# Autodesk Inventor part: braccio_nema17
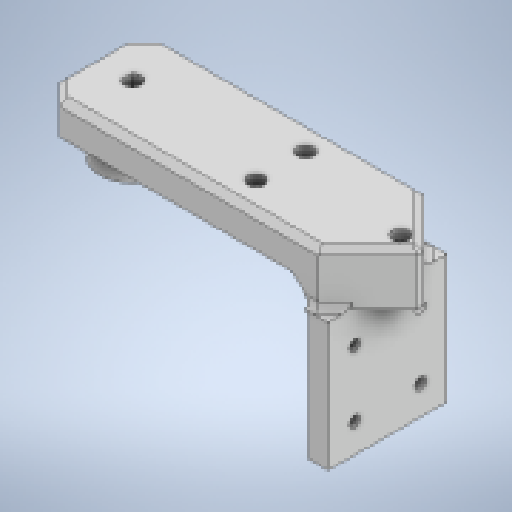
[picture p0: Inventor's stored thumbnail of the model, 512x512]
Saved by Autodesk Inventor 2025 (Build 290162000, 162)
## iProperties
Created: 2025-11
Part Number: braccio_nema17
Material: Generico
Document SubType Name: Modeling
Designer: R5800u
Density: 1 g/cm^3
Appearance: Default
Author: R5800u
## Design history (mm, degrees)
sketch "Schizzo1"
  geometry: L1 (2, 1.582)-(2, -1.582); C1 r 10 at (0, 0); A1 r 2.55 centre (0, 0) between (2, 1.582) and (2, -1.582); 1 further point
  constraints: 2 centre point, 2 coincident, 2 end point, 2 point on circle, 1 vertical
  dimensions: "d0" = 20 diameter of C1; "d1" = 5.1 diameter of A1; "d2" = 2 distance from line of point (0, 0) L1
extrude "Estrusione1" new body sketch "Schizzo1" distance "d3" = 20; taper "d4" = 0 deg
sketch "Schizzo2"
  geometry: L1 (-12.5, -16)-(87.5, -16); L2 (87.5, -16)-(87.5, 16); L3 (87.5, 16)-(-12.5, 16); L4 (-12.5, 16)-(-12.5, -16); L5 (0, 0)-(107, 0) reference; C1 r 10 at (0, 0) reference; C2 r 2.55 at (0, 0) reference; 1 further point
  constraints: 10 end point, 3 horizontal, 2 parallel, 1 perpendicular, 1 other
  dimensions: "d5" = 100 distance of L3.end L2.end
extrude "Estrusione2" join sketch "Schizzo2" distance "d6" = 10; taper "d7" = 0 deg
sketch "Schizzo3"
  geometry: L1 (18.5, -5)-(13.5, -5); L2 (13.5, -5)-(13.5, -15); L3 (13.5, -15)-(18.5, -15); L4 (18.5, -15)-(18.5, -5); L5 (6, -10)-(26, -10) reference; L6 (18.5, -5)-(13.5, -15); L7 (13.5, -5)-(18.5, -15); L8 (32, -10)-(0, -10) reference; 4 further points
  constraints: 12 end point, 3 midpoint, 2 parallel, 1 horizontal, 1 perpendicular
  dimensions: "d8" = 5 distance of L3.end L2.end
extrude "Estrusione3" join sketch "Schizzo3" stored distance "d9" = 10; taper "d10" = 0 deg
chamfer "Smusso1" distance "d11" = 6; stored, may be unused: second distance "d12" = 2, angle "d13" = 45 deg
sketch "Schizzo4"
  geometry: L1 (-6.5, -16)-(87.5, -16) reference; L2 (77.5, -16)-(77.5, 16); L3 (87.5, -16)-(87.5, -2.5) reference; L4 (87.5, 16)-(-6.5, 16) reference; L5 (77.5, -16)-(87.5, -16); L6 (87.5, -16)-(87.5, 16); L7 (87.5, 16)-(77.5, 16); L8 (77.5, 16)-(77.5, -16); 2 further points
  constraints: 10 end point, 2 parallel, 1 horizontal, 1 perpendicular, 1 point on line, 1 vertical
  dimensions: "d14" = 10 distance between parallel lines of L3 L2
node "Piano di lavoro1"
extrude "Estrusione4" join sketch "Schizzo4" stored distance "d15" = 10; taper "d16" = 0 deg
sketch "Schizzo5"
  geometry: L1 (77.5, -16)-(77.5, -2.5) reference; L2 (-6.5, 16)-(87.5, 16) reference; L3 (77.5, -16)-(69.5, -16); L4 (69.5, -16)-(69.5, 16); L5 (69.5, 16)-(77.5, 16); L6 (77.5, 16)-(77.5, -16); 3 further points
  constraints: 8 end point, 2 parallel, 1 horizontal, 1 perpendicular, 1 point on line
  dimensions: "d17" = 8 distance of L4.end L5.end
node "Piano di lavoro2"
extrude "Estrusione5" join sketch "Schizzo5" stored distance "d18" = 10; taper "d19" = 0 deg
sketch "Schizzo6"
  geometry: C1 r 1.45 at (6, -16.1) reference; C2 r 1.45 at (26, -16.1) reference; C3 r 1.45 at (6, -36.1) reference; C4 r 1.45 at (26, -36.1) reference; 1 further point
hole "Foro1" sketch "Schizzo6" at (6, -16.1), (26, -16.1), (6, -36.1), (26, -36.1) diameter "d20" = 3.2; stored, may be unused: countersink angle "d24" = 90 deg, drill point angle "d26" = 118 deg; dims "d21" = 6, "d22" = 6.5, "d23" = 3.4, "d25" = 12
chamfer "Smusso2" distance "d27" = 2; stored, may be unused: second distance "d28" = 2, angle "d29" = 45 deg
chamfer "Smusso3" distance "d30" = 5; stored, may be unused: second distance "d31" = 2, angle "d32" = 45 deg
sketch "Schizzo7"
  geometry: L1 (-2, 1.582)-(-2, -1.582); A1 r 2.55 centre (0, 0) between (-2, 1.582) and (-2, -1.582) reference; 3 further points
  constraints: 2 end point, 1 point on circle, 1 vertical, 2 other
  dimensions: "d33" = 2 distance from line of point (0, 0) L1
extrude "Estrusione6" join sketch "Schizzo7" distance "d34" = 17; taper "d35" = 0 deg
chamfer "Smusso4" distance "d36" = 2; stored, may be unused: second distance "d37" = 2, angle "d38" = 45 deg
chamfer "Smusso5" distance "d39" = 15; stored, may be unused: second distance "d40" = 2, angle "d41" = 45 deg
chamfer "Smusso6" distance "d42" = 2; stored, may be unused: second distance "d43" = 2, angle "d44" = 45 deg
sketch "Schizzo8"
  geometry: L1 (0, 14)-(94, 14) reference; L2 (0, 14)-(0, 0) reference; L3 (10, 0)-(0, 0) reference; L4 (10, 0)-(10, -39) reference; L5 (10, -39)-(16, -39) reference; L6 (18, -37)-(16, -39) reference; L7 (18, 1)-(18, -37) reference; L8 (23, 6)-(18, 1) reference; L9 (94, 6)-(23, 6) reference; L10 (94, 14)-(94, 6) reference; L11 (10, 0)-(18, 0); 1 further point
  constraints: 2 end point, 1 perpendicular, 1 point on line
extrude "Estrusione7" join sketch "Schizzo8" distance "d48" = 2; taper "d49" = 0 deg
mirror "Speculare1"
chamfer "Smusso8" distance "d50" = 15; stored, may be unused: second distance "d51" = 2, angle "d52" = 45 deg
fillet "Raccordo1" dims "d53" = 1.99
chamfer "Smusso9" distance "d54" = 2; stored, may be unused: second distance "d55" = 2, angle "d56" = 45 deg
chamfer "Smusso10" distance "d57" = 2; stored, may be unused: second distance "d58" = 2, angle "d59" = 45 deg
chamfer "Smusso11" distance "d60" = 2; stored, may be unused: second distance "d61" = 2, angle "d62" = 45 deg
sketch "Schizzo9"
  geometry: C1 r 1.35 at (45, -7.5) reference; C2 r 1.35 at (45, 7.5) reference; 1 further point
hole "Foro2" sketch "Schizzo9" at (45, 7.5), (45, -7.5) diameter "d63" = 2.7; stored, may be unused: countersink angle "d67" = 90 deg, drill point angle "d69" = 118 deg; dims "d64" = 6, "d65" = 5, "d66" = 2.9, "d68" = 12
sketch "Schizzo10"
  geometry: L1 (87.5, 1)-(87.5, -1) reference; L2 (87.5, 0)-(81.5, 0); 2 further points
  constraints: 2 end point, 1 coincident, 1 horizontal, 1 midpoint
  dimensions: "d78" = 6 distance from line of L1 L2.end
hole "Foro3" sketch "Schizzo10" at (81.5, 0) diameter "d71" = 2.7; stored, may be unused: countersink angle "d75" = 90 deg, drill point angle "d77" = 118 deg; dims "d72" = 6, "d73" = 5, "d74" = 2.9, "d76" = 12
node "Solido1"
node "Linea chiusa proiettata1"
node "Riferimento1"
node "Riferimento2"
node "Riferimento3"
node "Riferimento4"
node "Linea chiusa proiettata2"
node "Riferimento5"
node "Riferimento6"
